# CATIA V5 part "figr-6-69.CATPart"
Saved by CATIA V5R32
Part number: Part1
Bounding box of the stored display mesh (mm): x -44.666 to 44.666, y -69.79 to 69.79, z 0 to 74
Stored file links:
  D:\PROJECTS\Project 2022\CATIA V5 6R 2022\Resources\Part Files\c06_catia_v5_6r2022_prt\figr-6-69.CATPart
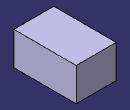
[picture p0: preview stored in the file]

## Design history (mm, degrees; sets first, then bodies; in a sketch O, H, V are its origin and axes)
Body1 (main body)
  Sketch1 on xy-plane, origin (0, 0, 0), H (1, 0, 0), V (0, 1, 0)
    line L1 (44.6658, 69.7903) -> (44.6658, -69.7903)
    line L2 (44.6658, -69.7903) -> (-44.6658, -69.7903)
    line L3 (-44.6658, -69.7903) -> (-44.6658, 69.7903)
    line L4 (-44.6658, 69.7903) -> (44.6658, 69.7903)
    vertical: L1 V, L3 V
    horizontal: L2 H, L4 H
    equidistance: L1 L3 O, L2 L4 O
  Pad1: profile Sketch1, direction (0, 0, 1), length 74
